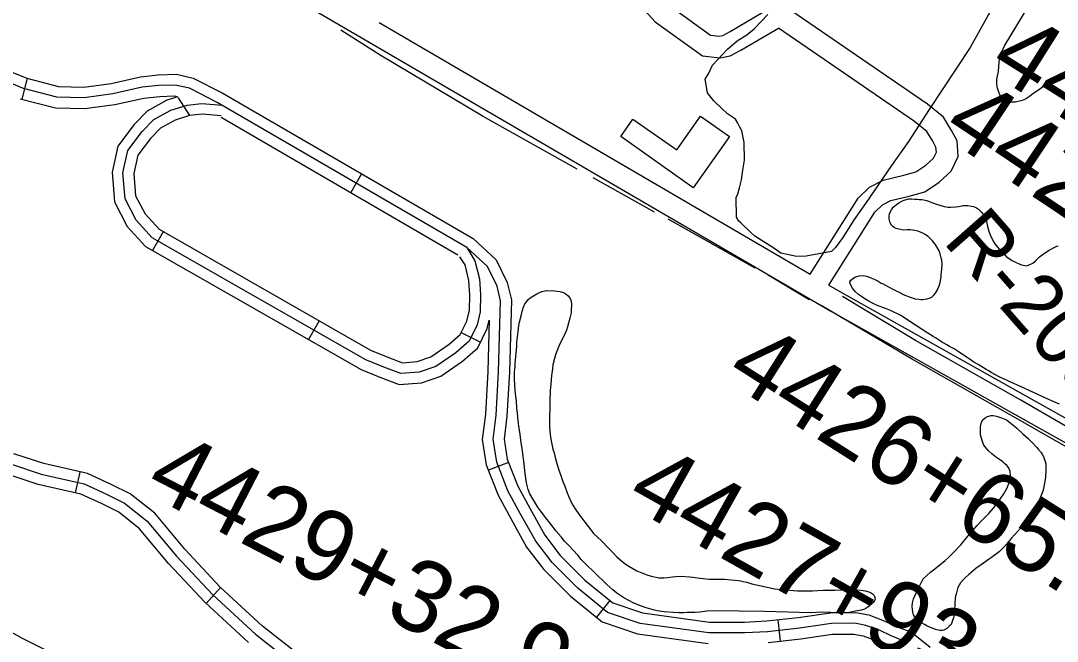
# Model space of a CAD drawing. Extents: x 3297753 to 3335611, y 652252 to 677623.
# Drawn here: x 3310374 to 3311817, y 658261 to 659124 of the extents above; entities that cross this region are included whole.
import ezdxf

# ---------------------------------------------------------------- set-up
doc = ezdxf.new("R2010")
doc.units = 0
for name, color, linetype in [('V-BLDG-OTLN', 7, 'Continuous'), ('V-RIVR-RANG-IDEN', 7, 'Continuous'), ('V-ROAD-CNTR', 7, 'Continuous'), ('V-SITE-VEGE', 7, 'Continuous'), ('V-SURV-IDEN', 7, 'Continuous'), ('V-TOPO-SHOR', 7, 'Continuous')]:
    doc.layers.add(name, color=color, linetype=linetype)

msp = doc.modelspace()

# ---------------------------------------------------------------- linework, layer by layer
at = {"layer": 'V-BLDG-OTLN'}
msp.add_lwpolyline([(3311360.3, 658962.6), (3311310.1, 658891.5), (3311209.1, 658963), (3311226.1, 658987.1), (3311287.1, 658944.1), (3311320.2, 658990.9)], close=True, dxfattribs=at)
at = {"layer": 'V-ROAD-CNTR'}
for p, q in [((3310383.2, 659043.7), (3310375.7, 659014.6)), ((3310609.2, 658991.9), (3310593.5, 659016.4)), ((3310848.5, 658910.8), (3310833.5, 658884.9)), ((3310572.4, 658830.4), (3310557.5, 658804.3)), ((3310789.5, 658706.4), (3310774.6, 658680.3)), ((3310987.1, 658690.2), (3311014.1, 658676.9)), ((3311052.9, 658509.4), (3311024.9, 658498.5)), ((3310450.3, 658466.9), (3310457, 658496.1)), ((3310632, 658313.2), (3310652.3, 658335.3)), ((3311194.1, 658317.5), (3311175.3, 658294.2)), ((3311427.8, 658290.6), (3311431, 658260.8))]:
    msp.add_line(p, q, dxfattribs=at)
for points in [[(3310089.7, 659646.9), (3310102.2, 659636.8), (3310393, 659398.3), (3310463, 659344.7), (3310528.1, 659297.1), (3310598, 659247.8), (3310662.5, 659209.1), (3311502.6, 658719.2), (3312183.9, 658337.2)], [(3311417.1, 659141.6), (3311422.1, 659155.2), (3311428.7, 659181.7), (3311428, 659196.9), (3311424.1, 659210.4), (3311415.9, 659225.5), (3311400, 659245.9), (3311378.2, 659266.9), (3311341.3, 659291.5), (3311333.6, 659293.1), (3311325.7, 659291), (3311317.2, 659286.4), (3311308.8, 659278.9), (3311261, 659205.9), (3311257.8, 659193.9), (3311257.3, 659179.9), (3311260.7, 659167.8), (3311266.9, 659155.6), (3311276.8, 659145), (3311334.2, 659103.9), (3311346.3, 659102.4), (3311351.1, 659103.4), (3311361.4, 659109), (3311417.1, 659141.6)], [(3311263.1, 659263.9), (3311246.6, 659238.8), (3311233.2, 659218.2), (3311227.9, 659198.3), (3311227.2, 659176.1), (3311232.7, 659156.8), (3311242.1, 659138.3), (3311256.9, 659122.4), (3311322.9, 659075), (3311347.6, 659072), (3311361.6, 659074.9), (3311376.2, 659082.9), (3311428.7, 659113.6)], [(3311498.8, 658756.2), (3311563, 658857.7), (3311573.3, 658867.5), (3311585.2, 658873.8), (3311610.7, 658879.7), (3311632.6, 658885.9), (3311652.3, 658899.3), (3311669.2, 658914.4), (3311678.8, 658935.1), (3311677.4, 658956.7), (3311669.4, 658971.3), (3311658.2, 658989.8), (3311636.1, 659007.8), (3311447.4, 659137.2)], [(3310873, 659121.2), (3311472.9, 658771.3)], [(3311472.9, 658771.3), (3311539.6, 658876.8), (3311555.5, 658892.1), (3311574.6, 658902.1), (3311603.2, 658908.8), (3311619.7, 658913.5), (3311633.8, 658923), (3311644.6, 658932.6), (3311648.4, 658940.8), (3311647.9, 658948.1), (3311643.4, 658956.3), (3311635.2, 658969.8), (3311618.1, 658983.7), (3311428.7, 659113.6)], [(3310351.5, 659056.5), (3310382.6, 659043.8), (3310426.6, 659032.5), (3310461.7, 659031.6), (3310499.7, 659036.7), (3310540.6, 659046), (3310565.5, 659048.5), (3310590.7, 659049.3), (3310613.9, 659044), (3310654.6, 659023.5), (3311003.8, 658820.7), (3311035.9, 658791.2), (3311051.3, 658759.6), (3311056.9, 658735.8), (3311054.2, 658634.8), (3311050.7, 658573.7), (3311046.7, 658541.9), (3311051.1, 658513.8), (3311065.7, 658476.5), (3311082.4, 658445.9), (3311103.4, 658408.2), (3311124.8, 658380.1), (3311159.2, 658345.7), (3311198.2, 658314.2), (3311239.4, 658300.3), (3311332.8, 658287.4), (3311381.3, 658287.2), (3311411.9, 658288.9), (3311456.1, 658293.7), (3311501.2, 658300.4), (3311536.2, 658300.7), (3311554.5, 658297.3), (3311575.9, 658289.3), (3311591.5, 658281.8), (3311613.7, 658273.2), (3311639.8, 658252.3)], [(3311606.1, 658260), (3311585.5, 658268.1), (3311570, 658275.5), (3311550.4, 658282.8), (3311534.9, 658285.7), (3311502.4, 658285.4), (3311458.1, 658278.8), (3311413.2, 658273.9), (3311381.7, 658272.2), (3311331.8, 658272.4), (3311236, 658285.6), (3311190.8, 658300.9), (3311149.2, 658334.5), (3311113.5, 658370.2), (3311090.8, 658400), (3311069.3, 658438.6), (3311052, 658470.1), (3311036.6, 658509.9), (3311031.5, 658541.7), (3311035.7, 658575.1), (3311039.2, 658635.4), (3311041.8, 658734.3), (3311037.1, 658754.5), (3311023.6, 658782.1), (3310994.9, 658808.5), (3310647.4, 659010.3), (3310608.8, 659029.8), (3310589.2, 659034.3), (3310566.5, 659033.5), (3310543, 659031.2), (3310502.4, 659021.9), (3310462.5, 659016.5), (3310424.5, 659017.6), (3310377.9, 659029.5), (3310344, 659043.3)], [(3310373.2, 659015.3), (3310422.4, 659002.6), (3310463.3, 659001.5), (3310505.1, 659007.1), (3310545.4, 659016.3), (3310567.5, 659018.6), (3310587.8, 659019.2), (3310592.5, 659018.1)], [(3310592.5, 659018.1), (3310577.2, 659013.4), (3310550.2, 658998.2), (3310532, 658979.6), (3310509.1, 658949.5), (3310501.1, 658913.1), (3310504.5, 658871.7), (3310522.4, 658837.7), (3310547.6, 658810), (3310847.7, 658638.5), (3310873.9, 658628.1), (3310900.9, 658617.7), (3310931.8, 658620), (3310958.6, 658629.2), (3310988.8, 658650.2), (3311010.1, 658668.9), (3311023.3, 658695.6), (3311026.1, 658707.1)], [(3310994.9, 658808.5), (3311006.3, 658790), (3311012.8, 658764.7), (3311013.9, 658742.4), (3311013.6, 658719.1), (3311009.1, 658700.8), (3310998, 658678.2), (3310979.5, 658662), (3310951.7, 658642.7), (3310928.7, 658634.8), (3310903.2, 658632.9), (3310879.4, 658642.1), (3310854.2, 658652.1), (3310557.1, 658821.8), (3310534.8, 658846.4), (3310519.2, 658875.9), (3310516.2, 658912.1), (3310523, 658943.1), (3310543.3, 658969.8), (3310559.4, 658986.2), (3310583.2, 658999.5), (3310605.7, 659006.5), (3310626.3, 659008.9), (3310654.5, 659006.2)], [(3310653, 658991.3), (3310626.5, 658993.8), (3310608.8, 658991.8), (3310589.1, 658985.7), (3310568.6, 658974.2), (3310554.7, 658959.9), (3310537, 658936.6), (3310531.4, 658911.1), (3310533.9, 658880.2), (3310547.2, 658855.1), (3310566.6, 658833.7), (3310860.8, 658665.6), (3310884.9, 658656), (3310905.4, 658648.1), (3310925.7, 658649.7), (3310944.9, 658656.2), (3310970.3, 658673.9), (3310985.8, 658687.5), (3310994.9, 658705.9), (3310998.6, 658721), (3310998.9, 658742.1), (3310997.9, 658762.4), (3310992.4, 658784.1), (3310985.3, 658795.4)], [(3310652.8, 658989.8), (3310982.6, 658798.3)], [(3311498.8, 658756.2), (3311517.5, 658745.3), (3312161.9, 658384)], [(3311026.1, 658707.1), (3311024.2, 658636), (3311020.8, 658576.5), (3311016.4, 658541.5), (3311022, 658505.9), (3311038.4, 658463.8), (3311056.2, 658431.4), (3311078.2, 658391.7), (3311102.2, 658360.3), (3311139.2, 658323.4), (3311183.5, 658287.5), (3311232.5, 658271), (3311330.7, 658257.4)], [(3310768.6, 658236.3), (3310710.7, 658281.9), (3310651.7, 658335.9), (3310602.3, 658388.9), (3310560.5, 658438.7), (3310526.6, 658465.6), (3310500.1, 658478.8), (3310467.2, 658493.8), (3310406.4, 658507.8), (3310364.3, 658521.5)], [(3310361, 658506.8), (3310402.4, 658493.3), (3310462.3, 658479.5), (3310493.6, 658465.2), (3310518.5, 658452.8), (3310550, 658427.9), (3310591, 658379), (3310641.2, 658325.2), (3310701, 658270.4), (3310759.7, 658224.2)], [(3310691.3, 658259), (3310630.6, 658314.5), (3310579.8, 658369), (3310539.5, 658417.1), (3310510.4, 658440.1), (3310487.2, 658451.7), (3310457.5, 658465.2), (3310398.4, 658478.8), (3310357.8, 658492.1)], [(3311414.4, 658258.9), (3311460, 658264), (3311503.6, 658270.4), (3311533.6, 658270.7), (3311546.4, 658268.3), (3311564.1, 658261.6), (3311579.5, 658254.3)]]:
    msp.add_lwpolyline(points, dxfattribs=at)
at = {"layer": 'V-SITE-VEGE'}
for points in [[(3311833.7, 659050.5), (3311815.4, 659041.7), (3311807.2, 659038.1), (3311802.5, 659035.4), (3311796.3, 659031.5), (3311792.3, 659028.7), (3311786.5, 659024.4), (3311782.6, 659021.9), (3311777.9, 659018.5), (3311772.6, 659014.8), (3311767.9, 659012.7), (3311758.5, 659010.7), (3311754.8, 659010.4), (3311748.9, 659010.4), (3311745.4, 659011.4), (3311741.6, 659013.7), (3311739.6, 659016), (3311736.8, 659020.8), (3311735.2, 659024.4), (3311733.7, 659030), (3311732.5, 659035.2), (3311732.4, 659038.3), (3311732.7, 659042.5), (3311734, 659049), (3311734.8, 659053.4), (3311735.9, 659066.8), (3311737.4, 659074.9), (3311739.4, 659080.6), (3311743.1, 659088.8), (3311784, 659156.4)], [(3311729.2, 659147.3), (3311695.6, 659086.4), (3311638.3, 659000.2), (3311609.7, 658955.8), (3311586.2, 658922.4), (3311549.6, 658869.5), (3311533.9, 658847.3), (3311518.4, 658822.3), (3311507.9, 658808.3), (3311502.6, 658802.7), (3311467.4, 658796.2), (3311453.8, 658795.8), (3311431.8, 658800.6), (3311420.7, 658808.4), (3311395.7, 658824), (3311390.1, 658829.3), (3311376.1, 658842.5), (3311373.3, 658845.1), (3311370.4, 658850.5), (3311369.6, 658877.7), (3311372.1, 658883.2), (3311374.6, 658891.5), (3311377, 658902.5), (3311379.3, 658916.1), (3311381.6, 658929.8), (3311380.9, 658954.3), (3311377.7, 658970.6), (3311374.8, 658975.9), (3311371.9, 658981.3), (3311369, 658986.7), (3311357.9, 658994.5), (3311341.1, 659010.3), (3311338.3, 659013), (3311329.8, 659023.6), (3311326.5, 659042.6), (3311331.7, 659050.9), (3311336.8, 659062), (3311357.9, 659084.4), (3311371.2, 659095.7), (3311384.6, 659104.3), (3311395.2, 659112.8), (3311413.7, 659132.4)], [(3311654.9, 658768.2), (3311655.1, 658771), (3311655.8, 658775.2), (3311656.2, 658778), (3311656.6, 658785.7), (3311656.2, 658790.9), (3311655.2, 658794.1), (3311653.8, 658799.8), (3311652.1, 658803.9), (3311648.9, 658809.4), (3311646.6, 658813.1), (3311643, 658817.8), (3311638.5, 658822.2), (3311636.9, 658823.5), (3311632, 658826.8), (3311628.5, 658828.7), (3311622.7, 658830.9), (3311618.3, 658832.1), (3311612, 658832.8), (3311607.8, 658832.9), (3311602.8, 658832.7), (3311598.6, 658833.2), (3311596, 658833.8), (3311592.3, 658834.8), (3311590.3, 658835.8), (3311587.4, 658837.9), (3311585.8, 658839.4), (3311584.2, 658842.6), (3311582.9, 658848.1), (3311582.8, 658851.1), (3311583.3, 658855.9), (3311585.8, 658861), (3311588.3, 658864.4), (3311592.8, 658868.4), (3311596, 658870.7), (3311601.1, 658873.5), (3311604.8, 658874.7), (3311610, 658875.9), (3311613.7, 658876), (3311618.3, 658875.7), (3311621.6, 658875.8), (3311624.4, 658875.3), (3311628.2, 658875), (3311630.8, 658874.6), (3311634.7, 658873.6), (3311637.6, 658872.6), (3311642.2, 658871.2), (3311650, 658868.4), (3311659.2, 658865.4), (3311664.7, 658864.5), (3311668.6, 658864.4), (3311675.4, 658864.8), (3311679.5, 658865.4), (3311685.2, 658866.6), (3311688.9, 658867), (3311692.1, 658866.8), (3311697.2, 658866.1), (3311700.2, 658865.6), (3311704.5, 658863.5), (3311706.9, 658861.8), (3311710.7, 658858.2), (3311715.9, 658851.6), (3311717.1, 658848.6), (3311718.3, 658844.5), (3311719.6, 658837.8), (3311720.4, 658834.5), (3311721.4, 658831.3), (3311723.3, 658826.1), (3311727.7, 658817.3), (3311730, 658813.6), (3311733.4, 658808.7), (3311735.9, 658805.9), (3311739.3, 658801.9), (3311743.5, 658798.1), (3311746.2, 658795.3), (3311754, 658790.1), (3311756.7, 658788.7), (3311759.3, 658787.7), (3311763.8, 658785.6), (3311766.9, 658784.4), (3311771.5, 658783.2), (3311774.1, 658783.1), (3311777.8, 658784.1), (3311782.7, 658786.8), (3311786.6, 658789.8), (3311792.1, 658795.2), (3311795.5, 658798.4), (3311804.7, 658804.3), (3311813.3, 658808.9), (3311815.9, 658810.1), (3311817.8, 658810.8)], [(3311819.8, 658590.6), (3311814.1, 658592.9), (3311797.7, 658600), (3311788, 658605), (3311761.2, 658616.8), (3311748.1, 658622.8), (3311736, 658628.7), (3311724.9, 658634.7), (3311721.3, 658636.8), (3311717.8, 658638.6), (3311706.6, 658645.5), (3311700.6, 658649), (3311694.2, 658653.4), (3311691.3, 658655.5), (3311683.5, 658660.7), (3311680.2, 658662.8), (3311673, 658667.2), (3311666.8, 658670.7), (3311663, 658673), (3311655.5, 658677.1), (3311647.3, 658682.6), (3311643.9, 658684.4), (3311636.4, 658689.2), (3311613, 658704.7), (3311603.9, 658710.5), (3311597.9, 658714.1), (3311584.6, 658720.6), (3311577.7, 658723.5), (3311564.9, 658728.3), (3311560.7, 658730.6), (3311557.6, 658731.8), (3311554.3, 658733.9), (3311548.9, 658736.8), (3311545.4, 658739.1), (3311540.2, 658743.1), (3311536, 658746.9), (3311533.7, 658749.4), (3311531.7, 658752), (3311529.4, 658756.1), (3311528.6, 658758.2), (3311528.1, 658760.8), (3311529.6, 658763.1), (3311535.1, 658767.2), (3311540.8, 658769.1), (3311547.5, 658769.3), (3311553.2, 658767.9), (3311557.2, 658766.1), (3311561.9, 658764.3), (3311567.4, 658761.4), (3311571.8, 658758.9), (3311574.3, 658757.9), (3311580.7, 658754.1), (3311588, 658750.6), (3311590.7, 658749), (3311599.3, 658744.7), (3311602.4, 658743.2), (3311611.9, 658739.1), (3311618.8, 658737.2), (3311623.8, 658736.4), (3311627.5, 658736.1), (3311629.7, 658736.2), (3311632.5, 658736.5), (3311635.6, 658737.2), (3311638.4, 658737.8), (3311642.1, 658739.4), (3311644.6, 658741.4), (3311647.1, 658744.8), (3311650, 658749.7), (3311652.7, 658756.3), (3311653.7, 658759.8), (3311654.6, 658764.9), (3311654.9, 658768.2)], [(3311073.4, 658724.5), (3311075.8, 658730), (3311078.3, 658733.3), (3311080, 658735.4), (3311083.2, 658738.3), (3311092.4, 658743.8), (3311099.3, 658747.3), (3311101.7, 658747.8), (3311106.5, 658748.4), (3311117, 658748), (3311124.6, 658747), (3311128.8, 658746), (3311131.5, 658744.8), (3311136.2, 658741.2), (3311138, 658738.6), (3311139.6, 658735.8), (3311140.6, 658730.6), (3311140.3, 658719.7), (3311140.1, 658717.3), (3311138.4, 658710), (3311135.1, 658697.9), (3311133.7, 658693.5), (3311130.8, 658687.1), (3311127.9, 658681.6), (3311123, 658671.2), (3311118.5, 658659.2), (3311116.9, 658654), (3311114.8, 658645.4), (3311114.1, 658639.5), (3311112.9, 658630.5), (3311111.7, 658618.4), (3311111.1, 658609.5), (3311110.5, 658594.2), (3311110.4, 658587.8), (3311109.9, 658570.6), (3311110, 658559.9), (3311110.4, 658553.1), (3311111.5, 658544.4), (3311112.3, 658539.4), (3311114.6, 658527.9), (3311116.3, 658523), (3311118.5, 658514.5), (3311122.9, 658498.7), (3311125.1, 658492.5), (3311128.6, 658482.8), (3311131.2, 658476.5), (3311134.8, 658467.2), (3311136.7, 658461.6), (3311140.2, 658454.3), (3311142.7, 658449.8), (3311146.6, 658443.6), (3311151, 658437.4), (3311159.4, 658426.1), (3311167.3, 658415.6), (3311171.4, 658410.7), (3311182.2, 658400.3), (3311192.6, 658389.5), (3311198.6, 658383.6), (3311203.8, 658378.1), (3311207.2, 658374.9), (3311215.2, 658368.4), (3311220.4, 658365), (3311231.5, 658358.6), (3311241, 658354.7), (3311245.6, 658353.1), (3311250, 658351.7), (3311253.3, 658350.7), (3311258.4, 658349.6), (3311262.3, 658349), (3311269.1, 658348.8), (3311274.1, 658349.2), (3311281.3, 658350.1), (3311285.8, 658350.8), (3311291.9, 658351), (3311305.5, 658350.3), (3311309.4, 658349.8), (3311316.2, 658348.7), (3311328.1, 658347.3), (3311332.7, 658347), (3311338.1, 658347), (3311341.6, 658347.1), (3311346.4, 658347), (3311349.5, 658347.1), (3311353.4, 658347), (3311373.1, 658345), (3311375.7, 658344.6), (3311379.5, 658343.6), (3311384.7, 658342.7), (3311388.7, 658341.3), (3311391.6, 658340.7), (3311423.4, 658333.4)], [(3311423.4, 658333.4), (3311432.6, 658332.6), (3311455.2, 658330.8), (3311464.1, 658330.7), (3311475.9, 658330.8), (3311490.7, 658331.7), (3311507.3, 658331.7), (3311526.9, 658332.3), (3311535.7, 658332.2), (3311543.8, 658331.8), (3311546.6, 658331.4), (3311549.5, 658330.8), (3311554.3, 658329.5), (3311556.9, 658328.4), (3311559.4, 658326.5), (3311561.7, 658324.4), (3311563, 658321.6), (3311563.3, 658319.2), (3311562.3, 658317.2), (3311560.4, 658314.8), (3311558.1, 658312.1), (3311556.4, 658310.7), (3311554.9, 658309.4), (3311553, 658308), (3311548.7, 658305.5), (3311543.9, 658304), (3311538.3, 658302.8), (3311531.6, 658301.5), (3311527, 658300.7), (3311518.9, 658300.2), (3311513.3, 658300.3), (3311488.8, 658301.3), (3311473.5, 658300.2), (3311409.1, 658301.9), (3311337.9, 658302.9), (3311329, 658302.4), (3311319, 658301.2), (3311312.2, 658300.8), (3311307.9, 658300.6), (3311301.5, 658300.7), (3311297, 658300.3), (3311289.8, 658300.3), (3311282.1, 658300.5), (3311269.6, 658301.5), (3311260, 658303.1), (3311254.1, 658304.5), (3311244.6, 658307.3), (3311238, 658309.5), (3311227.6, 658313.7), (3311213.6, 658320.9), (3311203.8, 658327.4), (3311198, 658332.3), (3311189.7, 658339.4), (3311184.8, 658344.5), (3311176.9, 658352.1), (3311171.3, 658357.9), (3311162.5, 658366.1), (3311154.2, 658374.6), (3311149.4, 658380.4), (3311136.3, 658394.4), (3311131.1, 658400.1), (3311126.2, 658405.8), (3311119.4, 658413.9), (3311115.3, 658419.5), (3311108.7, 658427.6), (3311104.2, 658432.9), (3311097.8, 658441.4), (3311093.9, 658447.2), (3311088, 658456.4), (3311082.7, 658465.9), (3311080.5, 658471.9), (3311078.1, 658481), (3311077, 658487.3), (3311075.6, 658497.1), (3311075, 658503.6), (3311071.8, 658528.8), (3311070.5, 658536.7), (3311069.1, 658548.2), (3311067.4, 658559.7), (3311066.5, 658567.1), (3311065.5, 658578), (3311064.7, 658584.9), (3311063.9, 658595), (3311063.1, 658601.3), (3311062.2, 658610.4), (3311061.1, 658624.6), (3311061.4, 658629.8), (3311061.4, 658634.8), (3311062.1, 658642.3), (3311062.4, 658647.5), (3311063.2, 658656.1), (3311063.5, 658661.7), (3311064.3, 658670.5), (3311064.5, 658676.6), (3311066.3, 658691.5), (3311067.3, 658699.8), (3311068.1, 658704.7), (3311071, 658715.2), (3311072, 658719.8), (3311073, 658722.3), (3311073.4, 658724.5)], [(3311688.4, 658349), (3311685.6, 658346.3), (3311681.8, 658342), (3311678.5, 658335.4), (3311677, 658329.9), (3311675.8, 658326.1), (3311675.2, 658323.7), (3311674.6, 658320), (3311674.1, 658314.5), (3311674.1, 658309.9), (3311673.7, 658306.2), (3311673.7, 658301.4), (3311672.9, 658296.3), (3311672.6, 658294.4), (3311672, 658292.4), (3311669.3, 658285.5), (3311668.1, 658283.5), (3311665.3, 658280.6), (3311662.8, 658278.6), (3311658.7, 658276.3), (3311656.3, 658275.5), (3311653.1, 658275.5), (3311647.1, 658277.2), (3311639.2, 658280.3), (3311635.4, 658281.9), (3311631.8, 658283.8), (3311628.5, 658285.8), (3311625.9, 658287.3), (3311624.1, 658288.5), (3311622.1, 658289.8), (3311619.6, 658291.9), (3311618.4, 658294.5), (3311616.6, 658297.3), (3311615.6, 658301), (3311615, 658305.5), (3311614.9, 658309), (3311615.4, 658314.3), (3311616.4, 658319.7), (3311619.2, 658325.5), (3311620.3, 658327.9), (3311629.1, 658345.5), (3311630.2, 658347.4), (3311640.4, 658356.7), (3311646.1, 658361.5), (3311660.8, 658373.2), (3311665.7, 658377.5), (3311671.8, 658383.6), (3311682.4, 658394.9), (3311692.3, 658406.9), (3311705, 658421.5), (3311711.3, 658428), (3311721.3, 658438.6), (3311727.4, 658445.3), (3311734.7, 658455.1), (3311742.1, 658465.8), (3311746.8, 658474.3), (3311748.3, 658477.6), (3311750.7, 658482.7), (3311751.5, 658485.3), (3311751.8, 658489.7), (3311751.7, 658492.3), (3311751.2, 658496.7), (3311748.8, 658502.5), (3311746.8, 658504.8), (3311743.4, 658508), (3311740.9, 658510.1), (3311737.6, 658512.6), (3311732.7, 658516), (3311725.8, 658521.4), (3311721.5, 658525.2), (3311719, 658527.8), (3311715.8, 658531.6), (3311714.2, 658534.4), (3311712.1, 658539.8), (3311709.9, 658548), (3311709.8, 658552.8), (3311709.8, 658559.6), (3311711.3, 658565.3), (3311713.2, 658568.7), (3311716.8, 658572), (3311719.8, 658573.4), (3311724.6, 658574.7), (3311727.6, 658574.8), (3311732.3, 658574), (3311739.3, 658571.6), (3311745.9, 658568.8), (3311750.4, 658565.6), (3311757.1, 658559.9), (3311760.3, 658557), (3311769, 658549.4), (3311776.2, 658542.6), (3311780.7, 658538.2), (3311788.1, 658530.3), (3311790.2, 658527.7), (3311794.2, 658523.3), (3311795.6, 658521.1), (3311797.5, 658517.7), (3311799.9, 658510.8), (3311800.6, 658507.5), (3311801, 658502.8), (3311800.9, 658499)], [(3311800.9, 658499), (3311800.1, 658488.5), (3311797.9, 658475.4), (3311796.9, 658471), (3311794.7, 658464.6), (3311793.1, 658460.4), (3311789.8, 658453.7), (3311784.2, 658444.2), (3311781.1, 658439.1), (3311775.6, 658431.3), (3311765.3, 658418.1), (3311752.9, 658404.2), (3311746.1, 658395.9), (3311741.7, 658391), (3311736, 658385.1), (3311725.1, 658377.1), (3311722.5, 658375.1), (3311714.2, 658369.4), (3311703.5, 658361.9), (3311693.5, 658353.5), (3311688.4, 658349)]]:
    msp.add_lwpolyline(points, dxfattribs=at)
at = {"layer": 'V-TOPO-SHOR'}
for p, q in [((3311256.2, 658857.6), (3311170.9, 658905.2)), ((3311396.3, 658779.5), (3311275.3, 658847.6)), ((3311471.2, 658735.7), (3311414.3, 658769.8))]:
    msp.add_line(p, q, dxfattribs=at)
for points in [[(3311148.7, 658917.3), (3311017.8, 658990.8), (3310874.5, 659075.9), (3310819.8, 659110.5)], [(3312088.4, 658411.8), (3312041.9, 658438.1), (3312014.8, 658453.3), (3311888.3, 658525.3), (3311766, 658596.1), (3311619.2, 658679.2), (3311518, 658740.4)], [(3312119.9, 658334.8), (3312112.6, 658352.3), (3312086.2, 658375.3), (3311938.5, 658468.6), (3311768.4, 658565.8), (3311614, 658653.6), (3311488, 658727.9)], [(3311848.3, 658104), (3311799.1, 658032.7), (3311767.3, 657973.6), (3311739.5, 657908.6), (3311717.3, 657855.5), (3311682.5, 657780.8), (3311665.2, 657753.9), (3311656.8, 657745.3), (3311647.9, 657741.3), (3311631.7, 657740.4), (3311529.1, 657776.2), (3311376.5, 657842.6), (3311207.9, 657914.9), (3311037.5, 657986), (3310992.4, 658002.2), (3310990.9, 658002.7), (3310858.4, 658054.9), (3310646.4, 658139.5), (3310478.5, 658213.3), (3310376.6, 658264.6), (3310287.6, 658314)]]:
    msp.add_lwpolyline(points, dxfattribs=at)

# ---------------------------------------------------------------- texts
at = {"layer": 'V-RIVR-RANG-IDEN'}
msp.add_text('R-209.0', height=83, rotation=311.2926, dxfattribs=at).set_placement((3311656.2, 658816.3))
at = {"layer": 'V-SURV-IDEN'}
for s, rotation, p in [('4419+56.5', 327.8211, (3311717.9, 659054.7)), ('4420+45.6', 326.1784, (3311653.2, 658965.9)), ('4426+65.5', 327.597, (3311351.6, 658625.1)), ('4429+32.9', 332.6436, (3310543.6, 658468.4)), ('4427+93.1', 330.7067, (3311213.4, 658452.4))]:
    msp.add_text(s, height=100, rotation=rotation, dxfattribs=at).set_placement(p)

doc.saveas('drawing.dxf')
